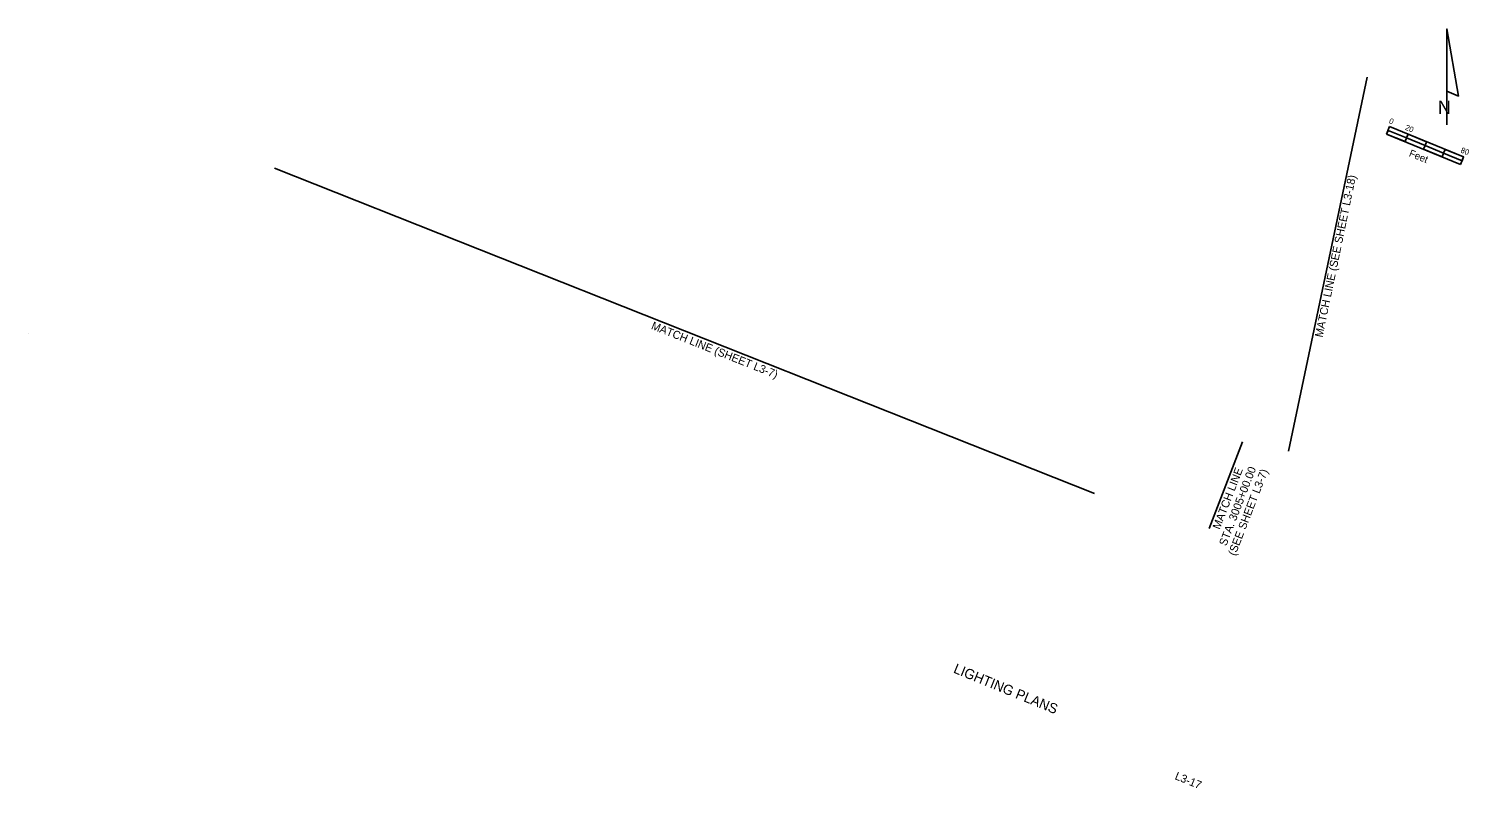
# Model space of a CAD drawing. Extents: x 917322 to 918761, y 637094 to 637852.
import ezdxf

# ---------------------------------------------------------------- set-up
doc = ezdxf.new("R2010")
doc.units = 0
for name, color, linetype in [('CGBack_ep', 7, 'Continuous'), ('CGFace_ep', 7, 'Continuous'), ('ConcSlabs_ep', 7, 'Continuous'), ('PavtConcJoints_ep', 7, 'Continuous'), ('SignMulti_ep', 7, 'Continuous'), ('Slopes_ep', 7, 'Continuous')]:
    doc.layers.add(name, color=color, linetype=linetype)

msp = doc.modelspace()

# ---------------------------------------------------------------- linework, layer by layer
at = {"layer": 'CGBack_ep'}
for p, q in [((918659.6, 637804.2), (918580.9, 637430.3)), ((918387, 637388), (917567.4, 637713.1)), ((918501.7, 637353.3), (918535, 637439.6))]:
    msp.add_line(p, q, dxfattribs=at)
at = {"layer": 'CGFace_ep'}
msp.add_line((917321.7, 637548.4), (917321.7, 637548.4), dxfattribs=at)
at = {"layer": 'PavtConcJoints_ep'}
msp.add_line((918739.3, 637756.3), (918739.3, 637852.3), dxfattribs=at)
msp.add_lwpolyline([(918739.3, 637789.9), (918739.3, 637852.3), (918750.8, 637785.1)], close=True, dxfattribs=at)
at = {"layer": 'SignMulti_ep'}
for p, q in [((918681.9, 637754.6), (918678.8, 637747.2)), ((918678.8, 637747.2), (918752.9, 637716.9)), ((918755.9, 637724.3), (918681.9, 637754.6)), ((918752.9, 637716.9), (918755.9, 637724.3))]:
    msp.add_line(p, q, dxfattribs=at)
for points in [[(918678.8, 637747.2), (918680.4, 637750.9), (918698.9, 637743.3), (918697.4, 637739.6)], [(918698.9, 637743.3), (918700.4, 637747), (918718.9, 637739.4), (918717.4, 637735.7)], [(918715.9, 637732), (918717.4, 637735.7), (918735.9, 637728.2), (918734.4, 637724.5)], [(918735.9, 637728.2), (918737.4, 637731.9), (918755.9, 637724.3), (918754.4, 637720.6)]]:
    msp.add_lwpolyline(points, close=True, dxfattribs=at)

# ---------------------------------------------------------------- texts
at = {"layer": 'CGBack_ep'}
for s, height, rotation, p in [('MATCH LINE (SEE SHEET L3-18)', 8, 78.2742, (918614.9, 637543.6)), ('MATCH LINE (SHEET L3-7)', 8, 338.3281, (917943.2, 637552.7)), ('MATCH LINE', 8, 68.8833, (918512.1, 637351.6)), ('STA. 3005+00.00', 8, 68.8833, (918518.6, 637335.1)), ('(SEE SHEET L3-7)', 8, 68.8833, (918527.7, 637325.3)), ('(SEE SHEET 4) ', 0.07, 248.8833, (918516.3, 637397.3)), ('STA. 6006+00.00', 0.07, 248.8833, (918517.3, 637396.9)), ('(SEE SHEET 4) ', 0.07, 248.8833, (918518.1, 637396.6)), ('STA. 6006+00.00', 0.07, 248.8833, (918518.2, 637396.5))]:
    msp.add_text(s, height=height, rotation=rotation, dxfattribs=at).set_placement(p)
at = {"layer": 'ConcSlabs_ep'}
msp.add_text('        LIGHTING PLANS         ', height=10, rotation=337.7838, dxfattribs=at).set_placement((918217.7, 637220.6))
at = {"layer": 'PavtConcJoints_ep'}
msp.add_text('N', height=13.4, dxfattribs=at).set_placement((918730.2, 637767.2))
at = {"layer": 'SignMulti_ep'}
for s, height, p in [('0', 5.6, (918680.8, 637758.2)), ('20', 5.6, (918696.9, 637751.7)), ('Feet', 7.2, (918700.7, 637725.3)), ('80', 5.6, (918752.4, 637729))]:
    msp.add_text(s, height=height, rotation=337.7838, dxfattribs=at).set_placement(p)
at = {"layer": 'Slopes_ep'}
msp.add_text('L3-17 ', height=8, rotation=337.7838, dxfattribs=at).set_placement((918466.6, 637102.9))

doc.saveas('drawing.dxf')
